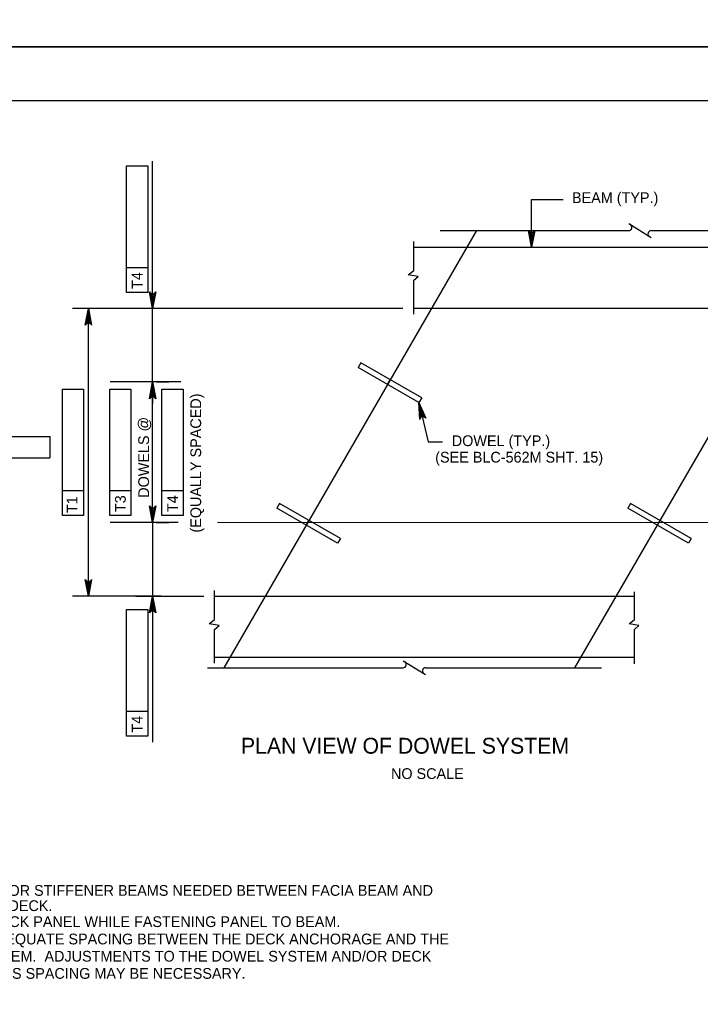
# Model space of a CAD drawing. Extents: x 638263 to 640360, y 293683 to 298655.
# Drawn here: x 639677 to 639866.7, y 296384.7 to 296661 of the extents above; entities that cross this region are included whole.
import ezdxf

# ---------------------------------------------------------------- set-up
doc = ezdxf.new("R2010")
doc.units = 0
for name, color, linetype in [('2', 7, 'Continuous'), ('3', 7, 'Continuous'), ('4', 7, 'Continuous'), ('PLT-BNDY', 7, 'Continuous')]:
    doc.layers.add(name, color=color, linetype=linetype)

# ---------------------------------------------------------------- blocks, each defined once
blk = doc.blocks.new('D')
at = {"layer": '3'}
for p, q in [((-0.48575, 0.574125), (-0.574125, 0.48575)), ((0.52325, -0.6115), (-0.574125, 0.48575)), ((0.6115, -0.52325), (-0.48575, 0.574125)), ((0.6115, -0.52325), (0.52325, -0.6115))]:
    blk.add_line(p, q, dxfattribs=at)

msp = doc.modelspace()

# ---------------------------------------------------------------- linework, layer by layer
at = {"layer": '2'}
for p, q in [((639316.46, 296638.46), (640102.46, 296638.46)), ((639804.37, 296602.15), (639733.89, 296480.22)), ((639902.21, 296602.15), (639831.73, 296480.22))]:
    msp.add_line(p, q, dxfattribs=at)
at = {"layer": '3'}
for p, q in [((639846.85, 296604.09), (639853.02, 296600.22)), ((639794.25, 296602.15), (639846.79, 296602.15)), ((639853, 296602.15), (639905.08, 296602.15)), ((639786.86, 296591), (639786.86, 296599.1)), ((639786.86, 296597.53), (639903.93, 296597.53)), ((639785.32, 296589.81), (639786.86, 296591)), ((639788.08, 296589.38), (639785.32, 296589.81)), ((639786.86, 296588.29), (639788.08, 296589.38)), ((639786.86, 296578.87), (639786.86, 296588.29)), ((639903.93, 296580.41), (639786.86, 296580.41)), ((639721.91, 296559.92), (639702.23, 296559.92)), ((639779.55, 296559.21), (639780.34, 296560.58)), ((639721.22, 296520.69), (639702.22, 296520.69)), ((639871.88, 296520.66), (639732.16, 296520.68)), ((639756.87, 296519.98), (639757.66, 296521.34)), ((639731.35, 296493.62), (639731.35, 296501.72)), ((639848.43, 296493.62), (639848.43, 296501.35)), ((639731.35, 296500.16), (639848.43, 296500.16)), ((639729.81, 296492.43), (639731.35, 296493.62)), ((639732.57, 296492.01), (639729.81, 296492.43)), ((639846.89, 296492.43), (639848.43, 296493.62)), ((639849.64, 296492.01), (639846.89, 296492.43)), ((639731.35, 296490.92), (639732.57, 296492.01)), ((639731.35, 296481.5), (639731.35, 296490.92)), ((639848.43, 296490.92), (639849.64, 296492.01)), ((639848.43, 296481.31), (639848.43, 296490.92)), ((639848.43, 296483.04), (639731.35, 296483.04)), ((639783.95, 296482.16), (639790.11, 296478.29)), ((639729.4, 296480.22), (639783.88, 296480.22)), ((639790.1, 296480.22), (639839.25, 296480.22))]:
    msp.add_line(p, q, dxfattribs=at)
for centre, start, end in [((639846.78, 296603.06), 270, 60), ((639853.08, 296601.25), 95.3286, 237.8672), ((639783.88, 296481.13), 270, 60), ((639790.18, 296479.32), 95.3286, 237.8672)]:
    msp.add_arc(centre, 0.909, start, end, dxfattribs=at)
at = {"layer": '4'}
for p, q in [((639706.78, 296620.2), (639712.68, 296620.2)), ((639706.78, 296591.79), (639706.78, 296620.2)), ((639712.68, 296620.2), (639712.68, 296584.9)), ((639714.06, 296586.42), (639714.06, 296621.51)), ((639819.74, 296610.87), (639828.54, 296610.87)), ((639706.78, 296584.9), (639706.78, 296591.79)), ((639712.68, 296591.79), (639706.78, 296591.79)), ((639714.06, 296559.92), (639714.06, 296586.42)), ((639712.68, 296584.9), (639706.78, 296584.9)), ((639783.8, 296580.41), (639691.68, 296580.41)), ((639696.18, 296500.16), (639696.18, 296580.41)), ((639712.51, 296580.42), (639709.56, 296580.42)), ((639714.06, 296520.68), (639714.06, 296559.92)), ((639715.11, 296559.92), (639718.56, 296559.92)), ((639688.9, 296557.95), (639694.8, 296557.95)), ((639688.9, 296529.54), (639688.9, 296557.95)), ((639694.8, 296557.95), (639694.8, 296522.65)), ((639702.11, 296522.65), (639702.11, 296557.95)), ((639702.11, 296557.95), (639708.01, 296557.95)), ((639708.01, 296557.95), (639708.01, 296522.65)), ((639714.06, 296556.92), (639714.06, 296553.92)), ((639716.65, 296557.95), (639722.55, 296557.95)), ((639716.65, 296529.54), (639716.65, 296557.95)), ((639722.55, 296557.95), (639722.55, 296522.65)), ((639650.45, 296544.69), (639685.41, 296544.69)), ((639685.41, 296544.69), (639685.41, 296538.78)), ((639790.88, 296543.19), (639794.9, 296543.19)), ((639642.89, 296538.78), (639685.41, 296538.78)), ((639688.9, 296522.65), (639688.9, 296529.54)), ((639694.8, 296529.54), (639688.9, 296529.54)), ((639708.01, 296529.54), (639702.11, 296529.54)), ((639716.65, 296522.65), (639716.65, 296529.54)), ((639722.55, 296529.54), (639716.65, 296529.54)), ((639714.06, 296523.68), (639714.06, 296526.68)), ((639694.8, 296522.65), (639688.9, 296522.65)), ((639708.01, 296522.65), (639702.11, 296522.65)), ((639722.55, 296522.65), (639716.65, 296522.65)), ((639714.06, 296520.68), (639714.06, 296459.48)), ((639715.09, 296520.68), (639718.56, 296520.68)), ((639716.41, 296500.16), (639691.68, 296500.16)), ((639709.38, 296500.17), (639728.35, 296500.16)), ((639715.42, 296500.17), (639709.56, 296500.17)), ((639706.78, 296461.13), (639706.78, 296496.43)), ((639706.78, 296496.43), (639712.68, 296496.43)), ((639712.68, 296496.43), (639712.68, 296461.13)), ((639714.06, 296497.17), (639714.06, 296494.17)), ((639712.68, 296468.02), (639706.78, 296468.02)), ((639712.68, 296461.13), (639706.78, 296461.13))]:
    msp.add_line(p, q, dxfattribs=at)
for points in [[(639819.74, 296597.53), (639819.74, 296610.87)], [(639819.74, 296597.53), (639818.87, 296602.19), (639819.12, 296601.84), (639819.43, 296601.65), (639819.74, 296601.6), (639820.06, 296601.65), (639820.37, 296601.84), (639820.62, 296602.19), (639819.74, 296597.53), (639820.37, 296601.84), (639820.06, 296601.65), (639819.74, 296597.53), (639819.74, 296601.6), (639819.43, 296601.65), (639819.74, 296597.53), (639819.12, 296601.84)], [(639714.06, 296580.41), (639713.19, 296585.07), (639713.43, 296584.71), (639713.75, 296584.53), (639714.06, 296584.47), (639714.37, 296584.53), (639714.68, 296584.71), (639714.93, 296585.07), (639714.06, 296580.41), (639714.68, 296584.71), (639714.37, 296584.53), (639714.06, 296580.41), (639714.06, 296584.47), (639713.75, 296584.53), (639714.06, 296580.41), (639713.43, 296584.71)], [(639696.18, 296580.41), (639697.05, 296575.75), (639696.8, 296576.11), (639696.49, 296576.29), (639696.18, 296576.35), (639695.86, 296576.29), (639695.55, 296576.11), (639695.3, 296575.75), (639696.18, 296580.41), (639695.55, 296576.11), (639695.86, 296576.29), (639696.18, 296580.41), (639696.18, 296576.35), (639696.49, 296576.29), (639696.18, 296580.41), (639696.8, 296576.11)], [(639714.06, 296559.92), (639714.93, 296555.26), (639714.68, 296555.62), (639714.37, 296555.81), (639714.06, 296555.86), (639713.75, 296555.81), (639713.43, 296555.62), (639713.19, 296555.26), (639714.06, 296559.92), (639713.43, 296555.62), (639713.75, 296555.81), (639714.06, 296559.92), (639714.06, 296555.86), (639714.37, 296555.81), (639714.06, 296559.92), (639714.68, 296555.62)], [(639788.3, 296554.16), (639790.89, 296543.19)], [(639788.3, 296554.16), (639790.22, 296549.82), (639789.9, 296550.11), (639789.55, 296550.22), (639789.24, 296550.2), (639788.94, 296550.08), (639788.68, 296549.83), (639788.52, 296549.42), (639788.3, 296554.16), (639788.68, 296549.83), (639788.94, 296550.08), (639788.3, 296554.16), (639789.24, 296550.2), (639789.55, 296550.22), (639788.3, 296554.16), (639789.9, 296550.11)], [(639714.06, 296520.69), (639713.19, 296525.35), (639713.43, 296524.99), (639713.75, 296524.8), (639714.06, 296524.75), (639714.37, 296524.8), (639714.68, 296524.99), (639714.93, 296525.35), (639714.06, 296520.69), (639714.68, 296524.99), (639714.37, 296524.8), (639714.06, 296520.69), (639714.06, 296524.75), (639713.75, 296524.8), (639714.06, 296520.69), (639713.43, 296524.99)], [(639696.18, 296500.16), (639695.3, 296504.82), (639695.55, 296504.47), (639695.86, 296504.28), (639696.18, 296504.23), (639696.49, 296504.28), (639696.8, 296504.47), (639697.05, 296504.82), (639696.18, 296500.16), (639696.8, 296504.47), (639696.49, 296504.28), (639696.18, 296500.16), (639696.18, 296504.23), (639695.86, 296504.28), (639696.18, 296500.16), (639695.55, 296504.47)], [(639714.06, 296500.17), (639714.93, 296495.51), (639714.68, 296495.87), (639714.37, 296496.05), (639714.06, 296496.1), (639713.75, 296496.05), (639713.43, 296495.87), (639713.19, 296495.51), (639714.06, 296500.17), (639713.43, 296495.87), (639713.75, 296496.05), (639714.06, 296500.17), (639714.06, 296496.1), (639714.37, 296496.05), (639714.06, 296500.17), (639714.68, 296495.87)]]:
    msp.add_lwpolyline(points, dxfattribs=at)
for points in [[(639819.74, 296597.53), (639819.78, 296597.65), (639819.72, 296597.65)], [(639713.56, 296556.92), (639714.56, 296556.92), (639714.06, 296559.92)], [(639788.3, 296554.16), (639788.3, 296554.03), (639788.36, 296554.05)]]:
    msp.add_lwpolyline(points, close=True, dxfattribs=at)
at = {"layer": 'PLT-BNDY'}
for points in [[(639276.46, 297247.46), (640117.46, 297247.46), (640117.46, 296653.46), (639276.46, 296653.46)], [(639276.46, 296653.46), (640117.46, 296653.46), (640117.46, 296059.46), (639276.46, 296059.46)]]:
    msp.add_lwpolyline(points, close=True, dxfattribs=at)

# ---------------------------------------------------------------- block references
at = {"layer": '4', "xscale": 12.59905511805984, "yscale": 12.599055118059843, "rotation": 14.970848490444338}
for p in [(639779.94, 296559.9), (639757.26, 296520.66), (639855.1, 296520.66)]:
    msp.add_blockref('D', p, dxfattribs=at)

# ---------------------------------------------------------------- texts
at = {"layer": '4'}
for s, height, p in [('BEAM (TYP.)', 3, (639830.99, 296609.84)), ('DOWEL (TYP.)', 3, (639797.48, 296542.03)), ('(SEE BLC-562M SHT. 15)', 3, (639792.85, 296537.44)), ('PLAN VIEW OF DOWEL SYSTEM', 4.4292, (639738.68, 296456.23)), ('NO SCALE', 3, (639780.52, 296449.17)), ('NO DOWELS OR STIFFENER BEAMS NEEDED BETWEEN FACIA BEAM AND ', 3, (639648.24, 296416.58)), ('OUTSIDE OF DECK.', 3, (639648.24, 296412.33)), ('PRELOAD DECK PANEL WHILE FASTENING PANEL TO BEAM.', 3, (639648.24, 296407.87)), ('PROVIDE ADEQUATE SPACING BETWEEN THE DECK ANCHORAGE AND THE ', 3, (639648.24, 296403.03)), ('DOWEL SYSTEM.  ADJUSTMENTS TO THE DOWEL SYSTEM AND/OR DECK', 3, (639648.24, 296398.23)), ("ANCHORAGE'S SPACING MAY BE NECESSARY.", 3, (639648.24, 296393.43))]:
    msp.add_text(s, height=height, dxfattribs=at).set_placement(p)
for s, p in [('T4', (639711.25, 296585.88)), ('(EQUALLY SPACED)', (639727.59, 296517.91)), ('DOWELS @', (639713.06, 296527.62)), ('T3', (639706.58, 296523.63)), ('T4', (639721.12, 296523.64)), ('T1', (639693.11, 296523.34)), ('T4', (639711.25, 296462.12))]:
    msp.add_text(s, height=3, rotation=90, dxfattribs=at).set_placement(p)

doc.saveas('drawing.dxf')
